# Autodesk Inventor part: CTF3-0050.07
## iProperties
Shininess: 64.0
Length Units: 11269
Angle Units: 11279
Time Units: 11290
Mass Units: 11283
Length Display Precision: 3
Angle Display Precision: 2
Compacted: True
Part Number: CTF3-0050.07
Document SubType Name: Modeling
Created: 2003-11
Designer: Lollo
Density: 0.0
Volumn: 0.0
Area: 0.0
PropertySet Name: Model Information
Control State: 0
Master: False
Checked Out: False
Author: Lollo
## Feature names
1. Estrusione1 [Extrusion]
2. Estrusione2 [Extrusion]
3. Foro1 [Hole]
4. Estrusione6 [Extrusion]
5. Estrusione7 [Extrusion]
6. Smusso1 [Chamfer]
7. Estrusione8 [Extrusion]
8. Specchio1 [Mirror]
9. Estrusione9 [Extrusion]
10. Specchio2 [Mirror]
11. Specchio3 [Mirror]
12. Estrusione10 [Extrusion]
13. Smusso2 [Chamfer]
14. Smusso3 [Chamfer]
15. Estrusione11 [Extrusion]
16. Foro2 [Hole]
17. Smusso4 [Chamfer]
